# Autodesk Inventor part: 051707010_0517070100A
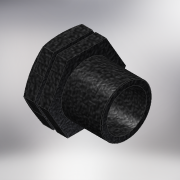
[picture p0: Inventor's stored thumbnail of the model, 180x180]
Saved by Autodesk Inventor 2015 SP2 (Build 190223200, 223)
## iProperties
Created: 2017-05
Part Number: 051707010_0517070100A
Material: Generic
Description: PLASSON PLUG 1"
Document SubType Name: Modeling
Designer: Кирилл
Density: 1 g/cm^3
Appearance: Black Cast
Author: Кирилл
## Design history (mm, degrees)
derived "051707.ipt"
feature "Solid1::051707.ipt"
tag "TaggingFeature1"
body "Solid1"
other parameters: "d1" = 33.249, "d2" = 36, "d3" = 25, "d5" = 19, "d6" = 4.85714, "d8" = 0.34, "d12" = 0, "d14" = 1.61905, "d15" = 34, "d16" = 1.94286, "d17" = 4.85714, "d19" = 0, "d21" = 2.42, "d29" = 0, "H_" = 34, "R_" = 33.249, "E_" = 36, "l_2" = 19, "d20" = 3.66667
